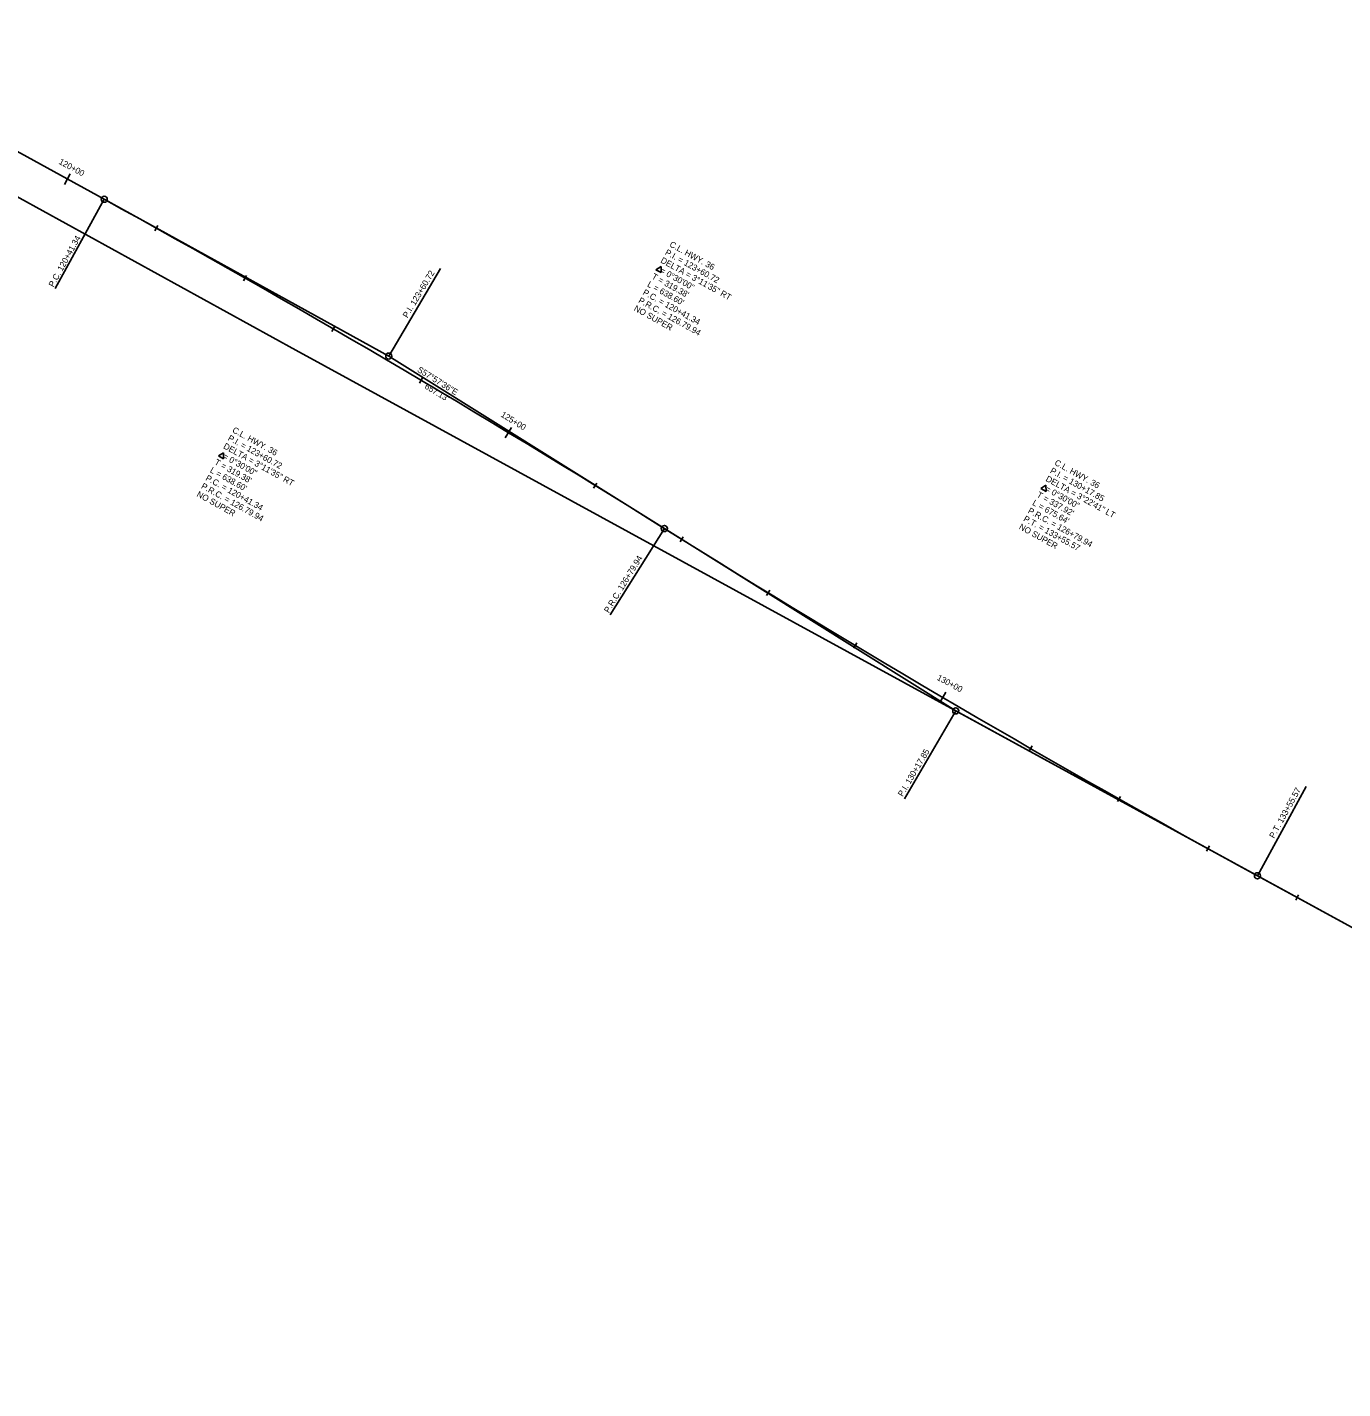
# Model space of a CAD drawing. Extents: x 1451272 to 1457767, y 301145 to 304591.
# Drawn here: x 1454895 to 1456188, y 301547 to 302885 of the extents above; entities that cross this region are included whole.
import ezdxf

# ---------------------------------------------------------------- set-up
doc = ezdxf.new("R2010")
doc.units = 0
for name, color, linetype in [('CL_Highway_1', 7, 'Continuous'), ('CL_Highway_1_text', 7, 'Continuous'), ('CL_Tangent', 7, 'Continuous'), ('CL_Tangent_Length', 7, 'Continuous'), ('CurveData_100', 7, 'Continuous'), ('PCPT_100_CL_ALT1', 7, 'Continuous'), ('PCPT_100_CL_Annot', 7, 'Continuous'), ('PI_100_CL_ALT1', 7, 'Continuous'), ('PI_100_CL_Annot', 7, 'Continuous'), ('Point_CL_Highway_2', 7, 'Continuous'), ('RD_Exist_CL', 7, 'Continuous'), ('STA_100_CL', 7, 'Continuous'), ('TICK_100_CL', 7, 'Continuous')]:
    doc.layers.add(name, color=color, linetype=linetype)

msp = doc.modelspace()

# ---------------------------------------------------------------- linework, layer by layer
at = {"layer": 'CL_Highway_1'}
for p, q in [((1454700.9, 302864.2), (1454970.6, 302715.7)), ((1454700.9, 302864.2), (1454970.6, 302715.7)), ((1454700.9, 302864.2), (1454970.6, 302715.7)), ((1454700.9, 302864.2), (1454970.6, 302715.7)), ((1454700.9, 302864.2), (1454970.6, 302715.7)), ((1454700.9, 302864.2), (1454970.6, 302715.7)), ((1454700.9, 302864.2), (1454970.6, 302715.7)), ((1456104, 302050.8), (1457026.2, 301546.7)), ((1456104, 302050.8), (1457026.2, 301546.7)), ((1456104, 302050.8), (1457026.2, 301546.7)), ((1456104, 302050.8), (1457026.2, 301546.7)), ((1456104, 302050.8), (1457026.2, 301546.7)), ((1456104, 302050.8), (1457026.2, 301546.7)), ((1456104, 302050.8), (1457026.2, 301546.7))]:
    msp.add_line(p, q, dxfattribs=at)
for centre, start, end in [((1449441.8, 292678.5), 57.95986, 61.15287), ((1449441.8, 292678.5), 57.95986, 61.15287), ((1449441.8, 292678.5), 57.95986, 61.15287), ((1449441.8, 292678.5), 57.95986, 61.15287), ((1449441.8, 292678.5), 57.95986, 61.15287), ((1449441.8, 292678.5), 57.95986, 61.15287), ((1449441.8, 292678.5), 57.95986, 61.15287), ((1461600.3, 312105.8), 237.95986, 241.33804), ((1461600.3, 312105.8), 237.95986, 241.33804), ((1461600.3, 312105.8), 237.95986, 241.33804), ((1461600.3, 312105.8), 237.95986, 241.33804), ((1461600.3, 312105.8), 237.95986, 241.33804), ((1461600.3, 312105.8), 237.95986, 241.33804), ((1461600.3, 312105.8), 237.95986, 241.33804)]:
    msp.add_arc(centre, 11459.2, start, end, dxfattribs=at)
at = {"layer": 'CL_Tangent'}
for p, q in [((1454970.6, 302715.7), (1455250.3, 302561.6)), ((1455250.3, 302561.6), (1455521.1, 302392.1)), ((1455521.1, 302392.1), (1455807.5, 302212.9)), ((1455807.5, 302212.9), (1456104, 302050.8))]:
    msp.add_line(p, q, dxfattribs=at)
for centre in [(1454970.6, 302715.7), (1455250.3, 302561.6), (1455521.1, 302392.1), (1455807.5, 302212.9), (1456104, 302050.8)]:
    msp.add_circle(centre, 3, dxfattribs=at)
at = {"layer": 'CurveData_100'}
for p, q in [((1455517.9, 302649.6), (1455512.7, 302646.5)), ((1455512.7, 302646.5), (1455518, 302643.6)), ((1455517.9, 302649.6), (1455518, 302643.6)), ((1455087.9, 302466.6), (1455082.8, 302463.6)), ((1455082.8, 302463.6), (1455088, 302460.6)), ((1455087.9, 302466.6), (1455088, 302460.6)), ((1455896.1, 302434.6), (1455891, 302431.5)), ((1455891, 302431.5), (1455896.2, 302428.6)), ((1455896.1, 302434.6), (1455896.2, 302428.6))]:
    msp.add_line(p, q, dxfattribs=at)
at = {"layer": 'PCPT_100_CL_ALT1'}
for points in [[(1454970.6, 302715.7), (1454922.3, 302628.1)], [(1455521.1, 302392.1), (1455468, 302307.4)], [(1456104, 302050.8), (1456152, 302138.5)]]:
    msp.add_lwpolyline(points, dxfattribs=at)
at = {"layer": 'PI_100_CL_ALT1'}
for points in [[(1455250.3, 302561.6), (1455301, 302647.8)], [(1455807.5, 302212.9), (1455757, 302126.6)]]:
    msp.add_lwpolyline(points, dxfattribs=at)
at = {"layer": 'Point_CL_Highway_2'}
for centre in [(1454970.6, 302715.7), (1454970.6, 302715.7), (1455521.1, 302392.1), (1455521.1, 302392.1), (1456104, 302050.8), (1456104, 302050.8), (1456104, 302050.8)]:
    msp.add_circle(centre, 3, dxfattribs=at)
at = {"layer": 'RD_Exist_CL'}
for p, q in [((1453278, 303603.4), (1455158.9, 302567.4)), ((1455158.9, 302567.4), (1457026.2, 301546.7))]:
    msp.add_line(p, q, dxfattribs=at)
at = {"layer": 'TICK_100_CL'}
for points in [[(1454937.3, 302740.8), (1454931.5, 302730.3)], [(1455023.3, 302689.8), (1455020.4, 302684.6)], [(1455110.5, 302640.7), (1455107.5, 302635.5)], [(1455197.2, 302590.9), (1455194.2, 302585.7)], [(1455283.5, 302540.3), (1455280.4, 302535.1)], [(1455370.9, 302491.5), (1455364.7, 302481.2)], [(1455454.7, 302436.8), (1455451.6, 302431.7)], [(1455539.7, 302384), (1455536.5, 302378.9)], [(1455624.7, 302331.5), (1455621.6, 302326.4)], [(1455710.3, 302279.7), (1455707.2, 302274.6)], [(1455797.7, 302231.3), (1455791.7, 302221)], [(1455882.6, 302178.4), (1455879.6, 302173.2)], [(1455969.5, 302128.9), (1455966.5, 302123.7)], [(1456056.8, 302080.2), (1456053.9, 302074.9)], [(1456144.4, 302032.1), (1456141.6, 302026.8)]]:
    msp.add_lwpolyline(points, dxfattribs=at)

# ---------------------------------------------------------------- texts
at = {"layer": 'CL_Highway_1_text'}
msp.add_text('S57%%d57\'36"E', height=6, rotation=328.0847, dxfattribs=at).set_placement((1455277.7, 302546.6))
at = {"layer": 'CL_Tangent_Length'}
msp.add_text("657.13'", height=6, rotation=328.8519, dxfattribs=at).set_placement((1455284.9, 302530.2))
at = {"layer": 'CurveData_100'}
for s, p in [('P.I. = 123+60.72', (1455521.2, 302661.7)), ('C.L. HWY. 36', (1455525.6, 302669.6)), ('DELTA = 3%%d11\'35" RT', (1455516.8, 302653.9)), ("T = 319.38'", (1455508.1, 302638.1)), ('  = 0%%d30\'00"', (1455512.4, 302646)), ('P.C. = 120+41.34', (1455499.3, 302622.4)), ("L = 638.60'", (1455503.7, 302630.3)), ('NO SUPER', (1455490.6, 302606.7)), ('P.R.C. = 126.79.94', (1455495, 302614.5)), ('C.L. HWY. 36', (1455095.9, 302487.1)), ('DELTA = 3%%d11\'35" RT', (1455087.1, 302471.3)), ('P.I. = 123+60.72', (1455091.5, 302479.2)), ('  = 0%%d30\'00"', (1455082.7, 302463.5)), ("L = 638.60'", (1455074, 302447.7)), ("T = 319.38'", (1455078.4, 302455.6)), ('P.I. = 130+17.85', (1455899.6, 302447.1)), ('C.L. HWY. 36', (1455904, 302455)), ('P.R.C. = 126.79.94', (1455065.3, 302432)), ('P.C. = 120+41.34', (1455069.6, 302439.9)), ('DELTA = 3%%d22\'41" LT', (1455895.3, 302439.2)), ('NO SUPER', (1455060.9, 302424.1)), ("T = 337.92'", (1455886.5, 302423.5)), ('  = 0%%d30\'00"', (1455890.9, 302431.4)), ('P.R.C. = 126+79.94', (1455877.8, 302407.8)), ("L = 675.64'", (1455882.2, 302415.6)), ('NO SUPER', (1455869, 302392)), ('P.T. = 133+55.57', (1455873.4, 302399.9))]:
    msp.add_text(s, height=6, rotation=330.951, dxfattribs=at).set_placement(p)
at = {"layer": 'PCPT_100_CL_Annot'}
for s, rotation, p in [('P.C. 120+41.34', 61.1975, (1454920.8, 302628.8)), ('P.R.C. 126+79.94', 58.5827, (1455466.5, 302308.6)), ('P.T. 133+55.57', 61.1975, (1456120.4, 302087.1))]:
    msp.add_text(s, height=6, rotation=rotation, dxfattribs=at).set_placement(p)
at = {"layer": 'PI_100_CL_Annot'}
for s, rotation, p in [('P.I. 123+60.72', 59.1069, (1455268.7, 302598.5)), ('P.I. 130+17.85', 59.3423, (1455755.3, 302128.1))]:
    msp.add_text(s, height=6, rotation=rotation, dxfattribs=at).set_placement(p)
at = {"layer": 'STA_100_CL'}
for s, rotation, p in [('120+00', 331.593, (1454925.4, 302750.8)), ('125+00', 328.1606, (1455359.8, 302502.5)), ('130+00', 331.593, (1455788.4, 302243.7))]:
    msp.add_text(s, height=6, rotation=rotation, dxfattribs=at).set_placement(p)

doc.saveas('drawing.dxf')
